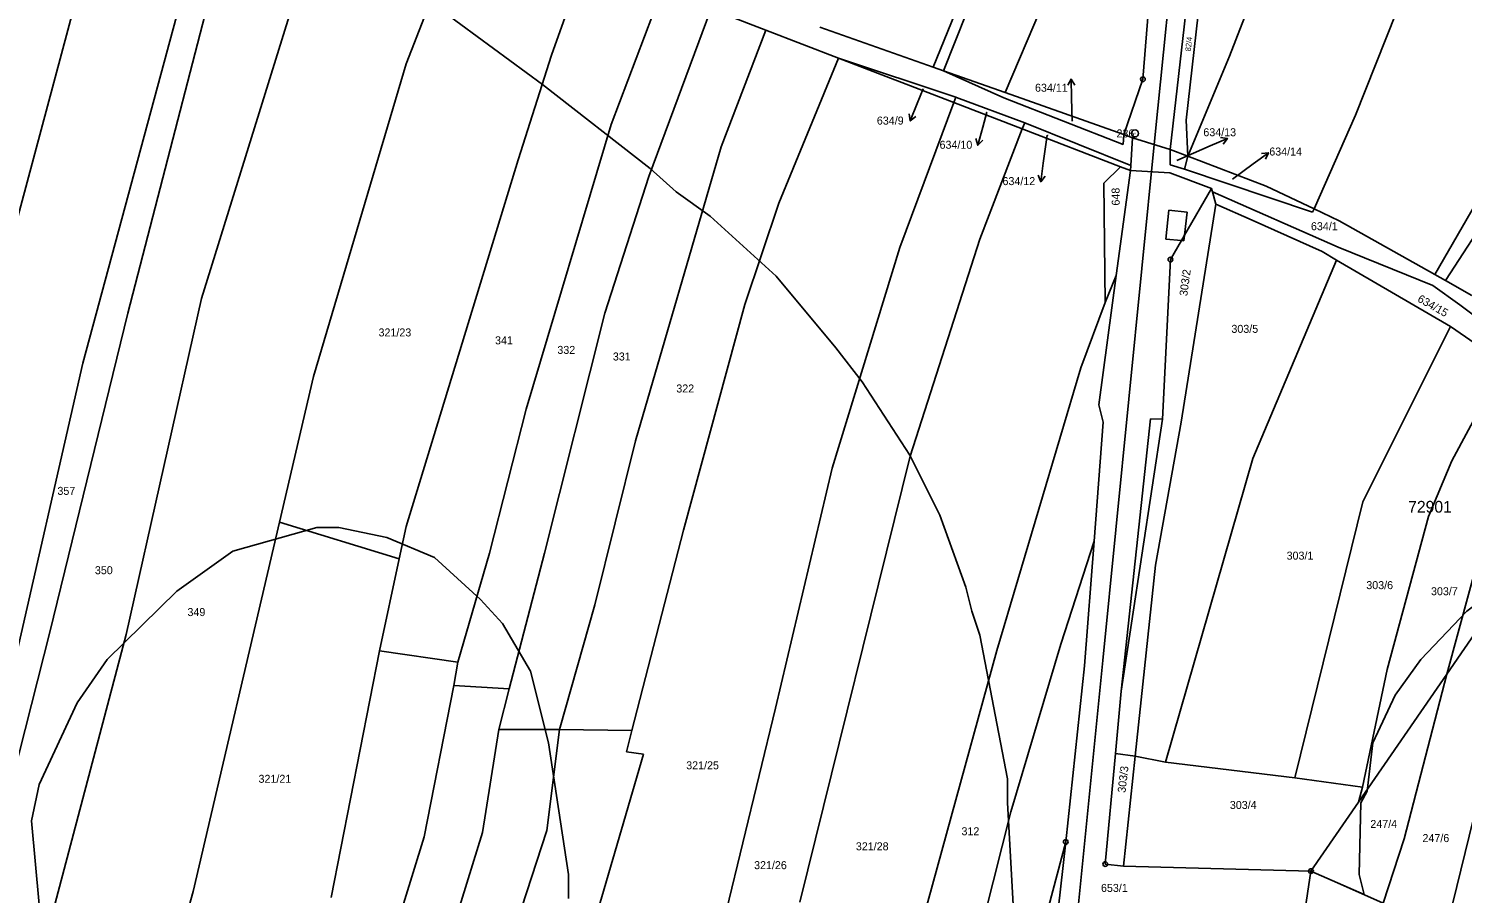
# Model space of a CAD drawing. Extents: x -743888 to -742027, y -1128394 to -1126768.
# Drawn here: x -743566.3 to -743261.6, y -1127677.1 to -1127493.3 of the extents above; entities that cross this region are included whole.
import ezdxf

# ---------------------------------------------------------------- set-up
doc = ezdxf.new("R2010")
doc.units = 0
for name, color, linetype in [('Vrstva 1', 7, 'Continuous'), ('Vrstva 10', 7, 'Continuous'), ('Vrstva 16', 7, 'Continuous'), ('Vrstva 17', 7, 'Continuous'), ('Vrstva 18', 7, 'Continuous'), ('Vrstva 24', 7, 'Continuous'), ('Vrstva 4', 7, 'Continuous'), ('Vrstva 52', 7, 'Continuous'), ('Vrstva 53', 7, 'Continuous'), ('Vrstva 6', 7, 'Continuous')]:
    doc.layers.add(name, color=color, linetype=linetype)

msp = doc.modelspace()

# ---------------------------------------------------------------- linework, layer by layer
at = {"layer": 'Vrstva 1'}
for points in [[(-743329.5, -1127504.03), (-743325.36, -1127452.28)], [(-743323.69, -1127519.01), (-743318.91, -1127476.67)], [(-743418.24, -1127490.3), (-743409.64, -1127493.62)], [(-743409.64, -1127493.62), (-743394.17, -1127499.58)], [(-743398.17, -1127492.95), (-743374.07, -1127501.47)], [(-743394.17, -1127499.58), (-743369.67, -1127509.02)], [(-743374.07, -1127501.47), (-743371.91, -1127502.23)], [(-743371.91, -1127502.23), (-743358.75, -1127506.88)], [(-743333.57, -1127515.78), (-743329.5, -1127504.03)], [(-743358.75, -1127506.88), (-743333.57, -1127515.78)], [(-743369.67, -1127509.02), (-743355.14, -1127514.62)], [(-743355.14, -1127514.62), (-743334.26, -1127522.66)], [(-743333.57, -1127515.78), (-743331.74, -1127516.48)], [(-743332.1, -1127522.4), (-743331.74, -1127516.48)], [(-743331.74, -1127516.48), (-743323.69, -1127519.01)], [(-743323.69, -1127519.01), (-743320, -1127520.42)], [(-743334.26, -1127522.66), (-743332.17, -1127523.47)], [(-743332.17, -1127523.47), (-743332.1, -1127522.4)], [(-743320, -1127520.42), (-743303.35, -1127526.75)], [(-743335.16, -1127545.74), (-743332.17, -1127523.47)], [(-743332.17, -1127523.47), (-743323.8, -1127523.97)], [(-743323.8, -1127523.97), (-743314.91, -1127527.24)], [(-743320.68, -1127537.21), (-743314.91, -1127527.24)], [(-743314.91, -1127527.24), (-743314.71, -1127527.98)], [(-743314.71, -1127527.98), (-743314.01, -1127530.6)], [(-743303.35, -1127526.75), (-743293.15, -1127531.6)], [(-743321.41, -1127576.97), (-743314.01, -1127530.6)], [(-743314.01, -1127530.6), (-743306.33, -1127533.99)], [(-743293.15, -1127531.6), (-743287.81, -1127534.14)], [(-743306.33, -1127533.99), (-743291.43, -1127540.69)], [(-743287.81, -1127534.14), (-743267.48, -1127545.58)], [(-743323.67, -1127542.37), (-743321.34, -1127538.34)], [(-743321.34, -1127538.34), (-743320.68, -1127537.21)], [(-743291.43, -1127540.69), (-743288.35, -1127542.49)], [(-743325.37, -1127576.31), (-743323.67, -1127542.37)], [(-743288.35, -1127542.49), (-743264.18, -1127556.62)], [(-743338.86, -1127573.29), (-743335.16, -1127545.74)], [(-743267.48, -1127545.58), (-743265.25, -1127546.83)], [(-743265.25, -1127546.83), (-743259.6, -1127550)], [(-743264.18, -1127556.62), (-743252.73, -1127564.48)], [(-743338.86, -1127573.29), (-743337.94, -1127576.95)], [(-743339.88, -1127602.23), (-743337.94, -1127576.95)], [(-743334.16, -1127634.18), (-743325.37, -1127576.31)], [(-743326.84, -1127607.36), (-743321.41, -1127576.97)], [(-743264.95, -1127630.5), (-743230.52, -1127580.51)], [(-743341.91, -1127628.76), (-743339.88, -1127602.23)], [(-743331.17, -1127647.95), (-743326.84, -1127607.36)], [(-743345.92, -1127666.2), (-743341.91, -1127628.76)], [(-743283.69, -1127657.72), (-743264.95, -1127630.5)], [(-743335.37, -1127647.41), (-743334.16, -1127634.18)], [(-743337.51, -1127670.9), (-743335.37, -1127647.41)], [(-743333.67, -1127671.36), (-743331.17, -1127647.95)], [(-743293.8, -1127672.4), (-743283.69, -1127657.72)], [(-743374.07, -1127772.46), (-743345.92, -1127666.2)], [(-743337.51, -1127670.9), (-743333.67, -1127671.36)], [(-743333.67, -1127671.36), (-743293.8, -1127672.4)], [(-743301.55, -1127724.14), (-743293.8, -1127672.4)], [(-743293.8, -1127672.4), (-743288.18, -1127674.9)], [(-743288.18, -1127674.9), (-743278.45, -1127679.23)]]:
    msp.add_lwpolyline(points, dxfattribs=at)
at = {"layer": 'Vrstva 10'}
for points in [[(-743322.08, -1127468.07), (-743326.96, -1127516.51)], [(-743326.96, -1127516.51), (-743338.02, -1127627.59)], [(-743338.02, -1127627.59), (-743347.15, -1127719.04)]]:
    msp.add_lwpolyline(points, dxfattribs=at)
at = {"layer": 'Vrstva 16'}
for p, q in [((-743345.49, -1127505.32), (-743344.77, -1127504)), ((-743377.78, -1127511.98), (-743378.95, -1127512.91)), ((-743363.54, -1127517.02), (-743364.6, -1127518.08)), ((-743313.04, -1127516.46), (-743311.55, -1127516.63)), ((-743304.35, -1127519.84), (-743302.86, -1127519.66)), ((-743350.31, -1127524.66), (-743351.23, -1127525.84))]:
    msp.add_line(p, q, dxfattribs=at)
for points in [[(-743344.68, -1127508), (-743344.77, -1127504), (-743343.99, -1127505.28)], [(-743376.23, -1127506.05), (-743377.48, -1127509.19)], [(-743344.57, -1127512.94), (-743344.68, -1127508)], [(-743377.48, -1127509.19), (-743378.95, -1127512.91), (-743379.17, -1127511.42)], [(-743362.69, -1127511.01), (-743363.56, -1127514.22)], [(-743363.56, -1127514.22), (-743364.6, -1127518.08), (-743364.99, -1127516.63)], [(-743349.88, -1127515.95), (-743350.69, -1127521.88)], [(-743315.22, -1127518.22), (-743311.55, -1127516.63), (-743312.44, -1127517.83)], [(-743322.32, -1127521.3), (-743315.22, -1127518.22)], [(-743306.07, -1127522.05), (-743302.86, -1127519.66), (-743303.46, -1127521.04)], [(-743350.69, -1127521.88), (-743351.23, -1127525.84), (-743351.8, -1127524.45)], [(-743310.46, -1127525.32), (-743306.07, -1127522.05)]]:
    msp.add_lwpolyline(points, dxfattribs=at)
at = {"layer": 'Vrstva 24'}
for p, q in [((-743329.55, -1127504.03), (-743329.45, -1127504.03)), ((-743331.24, -1127515.56), (-743331.14, -1127515.56)), ((-743323.72, -1127542.37), (-743323.62, -1127542.37)), ((-743345.97, -1127666.2), (-743345.87, -1127666.2)), ((-743337.56, -1127670.9), (-743337.46, -1127670.9)), ((-743293.85, -1127672.4), (-743293.75, -1127672.4))]:
    msp.add_line(p, q, dxfattribs=at)
for centre, radius in [((-743329.5, -1127504.03), 0.499), ((-743331.19, -1127515.56), 0.756), ((-743323.67, -1127542.37), 0.499), ((-743345.92, -1127666.2), 0.499), ((-743337.51, -1127670.9), 0.499), ((-743293.8, -1127672.4), 0.499)]:
    msp.add_circle(centre, radius, dxfattribs=at)
at = {"layer": 'Vrstva 4'}
for points in [[(-743324.66, -1127538.05), (-743324.03, -1127531.89)], [(-743324.03, -1127531.89), (-743320.11, -1127532.27)], [(-743320.68, -1127537.21), (-743320.11, -1127532.27)], [(-743324.66, -1127538.05), (-743321.34, -1127538.34)], [(-743321.34, -1127538.34), (-743320.82, -1127538.39)], [(-743320.82, -1127538.39), (-743320.68, -1127537.21)], [(-743334.16, -1127634.18), (-743327.93, -1127576.22)], [(-743327.93, -1127576.22), (-743325.37, -1127576.31)], [(-743356.23, -1127757.98), (-743345.92, -1127666.2)]]:
    msp.add_lwpolyline(points, dxfattribs=at)
at = {"layer": 'Vrstva 52'}
for points in [[(-743293.07, -1127296.72), (-743304.3, -1127331.19), (-743304.73, -1127332.52), (-743304.91, -1127333.26), (-743312.01, -1127362.15), (-743312.73, -1127365.1), (-743319.7, -1127398.48), (-743319.91, -1127400.47), (-743325.36, -1127452.28), (-743329.5, -1127504.03), (-743333.57, -1127515.78), (-743331.74, -1127516.48), (-743323.69, -1127519.01), (-743318.91, -1127476.67), (-743313.62, -1127423.64), (-743311.36, -1127402.88), (-743311.22, -1127402.11), (-743307.41, -1127381.95), (-743302.98, -1127364.26), (-743299.98, -1127352.31), (-743296.23, -1127335.74), (-743295.73, -1127333.53), (-743294.99, -1127330.28), (-743283.68, -1127298.96)], [(-743570.38, -1127436.88), (-743554.69, -1127442.75), (-743535.56, -1127453.38), (-743513.5, -1127466.5), (-743477.88, -1127489.88), (-743457.06, -1127505.13), (-743434.19, -1127523), (-743428.69, -1127528), (-743421.44, -1127533.13), (-743407.44, -1127545.88), (-743394.75, -1127561.13), (-743389.19, -1127568.38), (-743379.06, -1127584), (-743372.69, -1127596.75), (-743367.13, -1127612), (-743365.88, -1127617.13), (-743364.19, -1127622.25), (-743358.25, -1127652.75), (-743358.25, -1127657.88), (-743357, -1127680.75)], [(-743282.53, -1127677.41), (-743288.18, -1127674.9), (-743293.8, -1127672.4), (-743333.67, -1127671.36), (-743337.51, -1127670.9), (-743335.37, -1127647.41), (-743334.16, -1127634.18), (-743325.37, -1127576.31), (-743323.67, -1127542.37), (-743321.34, -1127538.34), (-743320.68, -1127537.21), (-743314.91, -1127527.24), (-743323.8, -1127523.97), (-743332.17, -1127523.47), (-743335.16, -1127545.74), (-743338.86, -1127573.29), (-743337.94, -1127576.95), (-743339.88, -1127602.23), (-743341.91, -1127628.76), (-743345.92, -1127666.2), (-743374.07, -1127772.46)], [(-743564, -1127679.5), (-743565.69, -1127661.75), (-743564, -1127654), (-743555.94, -1127636.63), (-743549.56, -1127627.38), (-743534.75, -1127612.88), (-743522.88, -1127604.38), (-743505.06, -1127599.38), (-743500.38, -1127599.38), (-743490.19, -1127601.5), (-743480, -1127605.75), (-743470.25, -1127614.63), (-743465.56, -1127619.75), (-743459.63, -1127629.88), (-743455.81, -1127645.13), (-743451.56, -1127673.13), (-743451.56, -1127678.25)], [(-743053.67, -1127722.32), (-743058.31, -1127718.5), (-743079.93, -1127701.11), (-743080.38, -1127700.75), (-743105, -1127679.13), (-743127.88, -1127660), (-743130, -1127657.5), (-743148.25, -1127642.13), (-743183.06, -1127617.63), (-743185.22, -1127616.53), (-743196.63, -1127610.75), (-743212.31, -1127605.25), (-743222.5, -1127604.38), (-743235.19, -1127605.75), (-743244.13, -1127607.38), (-743252.19, -1127610.75), (-743260.69, -1127617.13), (-743270.44, -1127627.38), (-743275.94, -1127635), (-743280.63, -1127645.13), (-743281.88, -1127655.38), (-743283.19, -1127657.88), (-743283.56, -1127673.13), (-743282.53, -1127677.41)]]:
    msp.add_lwpolyline(points, dxfattribs=at)
at = {"layer": 'Vrstva 6'}
for points in [[(-743311.15, -1127499.13), (-743275.71, -1127407.69)], [(-743579.58, -1127574.43), (-743546.31, -1127450.09)], [(-743554.73, -1127564.38), (-743526.58, -1127459.91)], [(-743545.21, -1127553.77), (-743521.89, -1127463.56)], [(-743284.35, -1127511.68), (-743264.86, -1127462.59)], [(-743486.04, -1127500.8), (-743474.35, -1127470.68)], [(-743320.31, -1127512.72), (-743315.66, -1127471.33)], [(-743374.07, -1127501.47), (-743363.18, -1127474.59)], [(-743371.91, -1127502.23), (-743362, -1127477.23)], [(-743455.14, -1127498.91), (-743448.36, -1127479.77)], [(-743529.52, -1127550.64), (-743508.94, -1127484.15)], [(-743442.53, -1127513.63), (-743431.85, -1127485.54)], [(-743434.5, -1127524.7), (-743421.29, -1127489.23)], [(-743358.75, -1127506.88), (-743351.05, -1127488.73)], [(-743419.11, -1127518.4), (-743409.64, -1127493.62)], [(-743462.28, -1127521.15), (-743455.14, -1127498.91)], [(-743505.77, -1127567.21), (-743486.04, -1127500.8)], [(-743406.86, -1127530.38), (-743394.17, -1127499.58)], [(-743394.17, -1127499.58), (-743369.28, -1127507.84)], [(-743320, -1127520.42), (-743311.15, -1127499.13)], [(-743371.91, -1127502.23), (-743359.08, -1127507.99)], [(-743369.67, -1127509.02), (-743369.28, -1127507.84)], [(-743369.28, -1127507.84), (-743369.13, -1127507.89)], [(-743369.13, -1127507.89), (-743354.63, -1127513.28)], [(-743359.08, -1127507.99), (-743333.72, -1127517.94)], [(-743381.16, -1127539.8), (-743369.67, -1127509.02)], [(-743460.53, -1127574.17), (-743442.53, -1127513.63)], [(-743355.14, -1127514.62), (-743354.63, -1127513.28)], [(-743354.63, -1127513.28), (-743332.1, -1127522.4)], [(-743320.31, -1127512.72), (-743320, -1127520.42)], [(-743293.15, -1127531.6), (-743284.35, -1127511.68)], [(-743267.48, -1127545.58), (-743248.98, -1127513.51)], [(-743364.14, -1127538.04), (-743355.14, -1127514.62)], [(-743333.72, -1127517.94), (-743333.57, -1127515.78)], [(-743437.32, -1127580.9), (-743419.11, -1127518.4)], [(-743323.7, -1127522.24), (-743323.69, -1127519.01)], [(-743486.02, -1127599.12), (-743462.28, -1127521.15)], [(-743337.82, -1127526.16), (-743334.26, -1127522.66)], [(-743323.7, -1127522.24), (-743320.65, -1127523.16)], [(-743320.65, -1127523.16), (-743320, -1127520.42)], [(-743320.65, -1127523.16), (-743293.49, -1127532.29)], [(-743443.83, -1127553.78), (-743434.5, -1127524.7)], [(-743337.82, -1127526.16), (-743337.56, -1127551.48)], [(-743314.71, -1127527.98), (-743288.02, -1127539.72)], [(-743414.11, -1127551.95), (-743406.86, -1127530.38)], [(-743293.49, -1127532.29), (-743293.15, -1127531.6)], [(-743265.25, -1127546.83), (-743254.82, -1127530.84)], [(-743378.99, -1127584.19), (-743364.14, -1127538.04)], [(-743395.56, -1127586.74), (-743381.16, -1127539.8)], [(-743288.02, -1127539.72), (-743267.92, -1127547.88)], [(-743306.14, -1127584.68), (-743288.35, -1127542.49)], [(-743337.56, -1127551.48), (-743335.16, -1127545.74)], [(-743545.56, -1127622.11), (-743529.52, -1127550.64)], [(-743267.92, -1127547.88), (-743262.15, -1127552)], [(-743427.12, -1127599.89), (-743414.11, -1127551.95)], [(-743342.72, -1127565.43), (-743337.56, -1127551.48)], [(-743262.15, -1127552), (-743250.66, -1127560.62)], [(-743561.74, -1127621.6), (-743545.21, -1127553.77)], [(-743456.63, -1127604.77), (-743443.83, -1127553.78)], [(-743282.79, -1127593.92), (-743264.18, -1127556.62)], [(-743570.37, -1127633.12), (-743554.73, -1127564.38)], [(-743360.58, -1127625.49), (-743342.72, -1127565.43)], [(-743263.84, -1127585.18), (-743252.73, -1127564.48)], [(-743512.98, -1127598.18), (-743505.77, -1127567.21)], [(-743468.34, -1127604.77), (-743460.53, -1127574.17)], [(-743446, -1127615.82), (-743437.32, -1127580.9)], [(-743402.41, -1127679.01), (-743378.99, -1127584.19)], [(-743407.6, -1127637.74), (-743395.56, -1127586.74)], [(-743324.73, -1127649.24), (-743306.14, -1127584.68)], [(-743268.85, -1127597.04), (-743263.84, -1127585.18)], [(-743297.22, -1127652.59), (-743282.79, -1127593.92)], [(-743531.28, -1127676.73), (-743512.98, -1127598.18)], [(-743512.98, -1127598.18), (-743487.51, -1127605.98)], [(-743487.51, -1127605.98), (-743486.02, -1127599.12)], [(-743277.65, -1127629.53), (-743268.85, -1127597.04)], [(-743438.1, -1127642.54), (-743427.12, -1127599.89)], [(-743346.97, -1127624.14), (-743339.88, -1127602.23)], [(-743475.06, -1127627.97), (-743468.34, -1127604.77)], [(-743464.14, -1127633.66), (-743456.63, -1127604.77)], [(-743264.95, -1127630.5), (-743257.74, -1127603.98)], [(-743491.75, -1127625.57), (-743487.51, -1127605.98)], [(-743453.46, -1127642.28), (-743446, -1127615.82)], [(-743265.43, -1127686.37), (-743248.78, -1127618.41)], [(-743573.61, -1127667.99), (-743561.74, -1127621.6)], [(-743562.33, -1127685.66), (-743545.56, -1127622.11)], [(-743502.02, -1127678), (-743491.75, -1127625.57)], [(-743491.75, -1127625.57), (-743475.06, -1127627.97)], [(-743392.64, -1127742.44), (-743360.58, -1127625.49)], [(-743357.58, -1127659.83), (-743346.97, -1127624.14)], [(-743475.93, -1127632.96), (-743475.06, -1127627.97)], [(-743282.86, -1127654.54), (-743277.65, -1127629.53)], [(-743274.02, -1127665.56), (-743264.95, -1127630.5)], [(-743482.22, -1127665.09), (-743475.93, -1127632.96)], [(-743475.93, -1127632.96), (-743464.14, -1127633.66)], [(-743466.39, -1127642.3), (-743464.14, -1127633.66)], [(-743418.02, -1127680.71), (-743407.6, -1127637.74)], [(-743469.86, -1127664.22), (-743466.39, -1127642.3)], [(-743466.39, -1127642.3), (-743453.46, -1127642.28)], [(-743456.19, -1127663.78), (-743453.46, -1127642.28)], [(-743453.46, -1127642.28), (-743438.1, -1127642.54)], [(-743439.27, -1127647.07), (-743438.1, -1127642.54)], [(-743460.31, -1127732.22), (-743435.59, -1127647.51)], [(-743439.27, -1127647.07), (-743435.59, -1127647.51)], [(-743335.37, -1127647.41), (-743331.17, -1127647.95)], [(-743331.17, -1127647.95), (-743324.73, -1127649.24)], [(-743324.73, -1127649.24), (-743297.22, -1127652.59)], [(-743297.22, -1127652.59), (-743282.86, -1127654.54)], [(-743283.69, -1127657.72), (-743282.86, -1127654.54)], [(-743366.95, -1127696.84), (-743357.58, -1127659.83)], [(-743506.51, -1127743.94), (-743482.22, -1127665.09)], [(-743494.95, -1127745.55), (-743469.86, -1127664.22)], [(-743479.83, -1127736.34), (-743456.19, -1127663.78)], [(-743278.45, -1127679.23), (-743274.02, -1127665.56)], [(-743550.89, -1127746.78), (-743531.28, -1127676.73)]]:
    msp.add_lwpolyline(points, dxfattribs=at)

# ---------------------------------------------------------------- texts
at = {"layer": 'Vrstva 16'}
for s, p in [('634/11', (-743352.44, -1127506.7)), ('634/9', (-743386.04, -1127513.68)), ('634/10', (-743372.72, -1127518.82)), ('634/13', (-743316.67, -1127516.16)), ('634/14', (-743302.66, -1127520.26)), ('634/12', (-743359.35, -1127526.55))]:
    msp.add_text(s, height=1.7, dxfattribs=at).set_placement(p)
at = {"layer": 'Vrstva 17'}
msp.add_text('236', height=1.7, dxfattribs=at).set_placement((-743335.12, -1127516.41))
at = {"layer": 'Vrstva 18'}
for s, height, rotation, p in [('82/4', 1.19, 83.2049, (-743319.38, -1127498.17)), ('648', 1.7, 90.6377, (-743334.44, -1127530.89)), ('303/2', 1.7, 82.2682, (-743320.1, -1127550.23)), ('634/15', 1.7, 330.4129, (-743271.32, -1127551.21)), ('303/3', 1.7, 83.2385, (-743333.23, -1127655.82))]:
    msp.add_text(s, height=height, rotation=rotation, dxfattribs=at).set_placement(p)
for s, height, p in [('634/9', 0.1, (-743376.23, -1127506.05)), ('634/10', 0.1, (-743362.69, -1127511.01)), ('634/11', 0.1, (-743344.57, -1127512.94)), ('634/12', 0.1, (-743349.88, -1127515.95)), ('634/13', 0.1, (-743322.32, -1127521.3)), ('634/14', 0.1, (-743310.46, -1127525.32)), ('634/1', 1.7, (-743293.81, -1127536.14)), ('303/5', 1.7, (-743310.71, -1127557.96)), ('321/23', 1.7, (-743491.92, -1127558.72)), ('341', 1.7, (-743467.17, -1127560.4)), ('332', 1.7, (-743453.93, -1127562.44)), ('331', 1.7, (-743442.14, -1127563.84)), ('322', 1.7, (-743428.65, -1127570.64)), ('357', 1.7, (-743560.15, -1127592.41)), ('303/1', 1.7, (-743298.98, -1127606.18)), ('350', 1.7, (-743552.19, -1127609.28)), ('303/6', 1.7, (-743282.05, -1127612.45)), ('303/7', 1.7, (-743268.3, -1127613.75)), ('349', 1.7, (-743532.52, -1127618.18)), ('321/25', 1.7, (-743426.55, -1127650.76)), ('321/21', 1.7, (-743517.42, -1127653.63)), ('303/4', 1.7, (-743311.04, -1127659.19)), ('312', 1.7, (-743368.06, -1127664.78)), ('247/4', 1.7, (-743281.19, -1127663.23)), ('321/28', 1.7, (-743390.5, -1127667.98)), ('247/6', 1.7, (-743270.11, -1127666.23)), ('321/26', 1.7, (-743412.13, -1127671.99)), ('653/1', 1.7, (-743338.42, -1127676.83))]:
    msp.add_text(s, height=height, dxfattribs=at).set_placement(p)
at = {"layer": 'Vrstva 53'}
msp.add_text('72901', height=2.5, dxfattribs=at).set_placement((-743273.16, -1127596.19))

doc.saveas('drawing.dxf')
